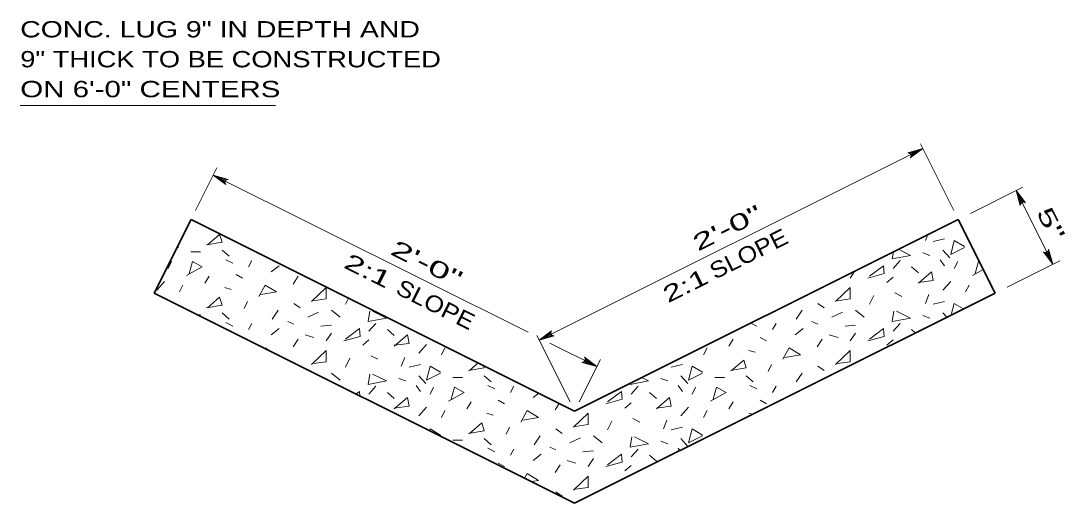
# Model space of a CAD drawing. Extents: x -10 to 104, y -162 to -1.
# Drawn here: x 35.7 to 99, y -82.7 to -53.5 of the extents above; entities that cross this region are included whole.
import ezdxf
from ezdxf.enums import TextEntityAlignment as Align

# ---------------------------------------------------------------- set-up
doc = ezdxf.new("R2010")
doc.units = 0
doc.header["$LTSCALE"] = 0.4
for name, color, linetype, lineweight in [('1', 7, 'Continuous', 35), ('10', 7, 'Continuous', 13), ('12', 7, 'Continuous', 53), ('6', 7, 'Continuous', 13)]:
    doc.layers.add(name, color=color, linetype=linetype, lineweight=lineweight)
doc.layers.add('13', color=7, linetype='Continuous')

msp = doc.modelspace()

# ---------------------------------------------------------------- linework, layer by layer
at = {"layer": '1'}
for p, q in [((46.0245, -65.5251), (69.2796, -77.1526)), ((92.5347, -65.5251), (69.2796, -77.1526)), ((92.5347, -65.5251), (94.7707, -69.9972)), ((94.7707, -69.9972), (69.2796, -82.7428))]:
    msp.add_line(p, q, dxfattribs=at)
at = {"layer": '1', "lineweight": 13}
for p, q in [((83.6592, -75.5428), (83.6702, -75.5475)), ((61.1548, -78.6669), (61.1413, -78.6737))]:
    msp.add_line(p, q, dxfattribs=at)
at = {"layer": '1'}
msp.add_lwpolyline([(46.0245, -65.5251), (43.7884, -69.9972), (69.2796, -82.7428)], dxfattribs=at)
at = {"layer": '10'}
for p, q in [((35.6689, -58.6171), (51.1348, -58.6171)), ((90.385, -61.2257), (67.1299, -72.8532)), ((92.2598, -64.9754), (90.2463, -60.9484)), ((46.2993, -64.9754), (47.5914, -62.3913)), ((47.3701, -62.8338), (66.4527, -72.3751)), ((93.2702, -65.1573), (96.4536, -63.5656)), ((98.275, -68.2451), (96.0389, -63.773)), ((95.5063, -69.6295), (98.6897, -68.0378)), ((69.0047, -76.6029), (66.9912, -72.5759)), ((67.7675, -73.0325), (70.6252, -74.4614)), ((69.5544, -76.6029), (70.8465, -74.0188))]:
    msp.add_line(p, q, dxfattribs=at)
for points in [[(90.385, -61.2257), (89.6295, -61.7988), (89.6714, -61.7222), (89.6766, -61.6497), (89.6583, -61.5891), (89.6207, -61.5379), (89.5596, -61.4986), (89.4732, -61.4862), (90.385, -61.2257), (89.5596, -61.4986), (89.6207, -61.5379), (90.385, -61.2257), (89.6583, -61.5891), (89.6766, -61.6497), (90.385, -61.2257), (89.6714, -61.7222)], [(47.3701, -62.8338), (48.2819, -63.0944), (48.1954, -63.1067), (48.1343, -63.1461), (48.0968, -63.1972), (48.0784, -63.2579), (48.0836, -63.3304), (48.1256, -63.407), (47.3701, -62.8338), (48.0836, -63.3304), (48.0784, -63.2579), (47.3701, -62.8338), (48.0968, -63.1972), (48.1343, -63.1461), (47.3701, -62.8338), (48.1954, -63.1067)], [(96.0389, -63.773), (96.612, -64.5285), (96.5354, -64.4865), (96.463, -64.4813), (96.4023, -64.4997), (96.3511, -64.5372), (96.3118, -64.5983), (96.2994, -64.6848), (96.0389, -63.773), (96.3118, -64.5983), (96.3511, -64.5372), (96.0389, -63.773), (96.4023, -64.4997), (96.463, -64.4813), (96.0389, -63.773), (96.5354, -64.4865)], [(98.275, -68.2451), (97.7018, -67.4896), (97.7785, -67.5316), (97.8509, -67.5367), (97.9116, -67.5184), (97.9627, -67.4808), (98.0021, -67.4198), (98.0144, -67.3333), (98.275, -68.2451), (98.0021, -67.4198), (97.9627, -67.4808), (98.275, -68.2451), (97.9116, -67.5184), (97.8509, -67.5367), (98.275, -68.2451), (97.7785, -67.5316)], [(67.1299, -72.8532), (67.8854, -72.2801), (67.8434, -72.3567), (67.8382, -72.4292), (67.8566, -72.4899), (67.8941, -72.541), (67.9552, -72.5803), (68.0417, -72.5927), (67.1299, -72.8532), (67.9552, -72.5803), (67.8941, -72.541), (67.1299, -72.8532), (67.8566, -72.4899), (67.8382, -72.4292), (67.1299, -72.8532), (67.8434, -72.3567)], [(70.6252, -74.4614), (69.7134, -74.2009), (69.7999, -74.1885), (69.8609, -74.1491), (69.8985, -74.098), (69.9168, -74.0373), (69.9117, -73.9649), (69.8697, -73.8882), (70.6252, -74.4614), (69.9117, -73.9649), (69.9168, -74.0373), (70.6252, -74.4614), (69.8985, -74.098), (69.8609, -74.1491), (70.6252, -74.4614), (69.7999, -74.1885)]]:
    msp.add_lwpolyline(points, dxfattribs=at)
at = {"layer": '6'}
for p, q in [((90.6853, -66.4498), (90.5429, -66.8058)), ((91.6347, -65.9751), (91.6019, -66.0115)), ((91.7078, -66.6999), (91.0194, -66.8587)), ((45.2694, -67.2294), (45.1399, -67.2941)), ((45.2147, -67.1445), (45.2694, -67.1764)), ((46.0108, -67.4941), (46.5932, -67.4941)), ((47.917, -67.3882), (48.3406, -67.7589)), ((90.384, -67.5471), (90.8076, -67.7059)), ((91.6019, -67.3882), (92.0255, -67.8648)), ((44.8458, -68.0766), (44.634, -68.5002)), ((48.1288, -67.9707), (48.5524, -68.1825)), ((49.5056, -68.3943), (49.7174, -68.0237)), ((51.3588, -68.3414), (50.8823, -68.712)), ((88.5837, -68.5002), (89.0073, -68.0237)), ((91.4431, -67.9707), (91.7078, -68.3414)), ((92.5021, -68.0766), (92.2903, -68.5002)), ((46.858, -69.4004), (47.1227, -68.9768)), ((48.7642, -68.8709), (49.1349, -69.0827)), ((52.5238, -68.9768), (52.2061, -69.4533)), ((85.9891, -69.0827), (86.2738, -68.6555)), ((89.6957, -68.3943), (90.1193, -68.765)), ((93.4022, -68.9238), (94.0532, -68.5622)), ((44.4222, -69.2945), (43.9457, -69.824)), ((45.5342, -69.5063), (45.3224, -69.9299)), ((88.213, -69.3474), (88.5837, -69.0297)), ((92.0785, -69.2945), (91.6019, -69.824)), ((93.1904, -69.5063), (92.9786, -69.9299)), ((48.0759, -69.6652), (48.4465, -69.7711)), ((87.154, -70.6712), (87.4187, -70.1417)), ((88.6896, -69.9829), (89.1132, -70.1947)), ((90.7547, -70.0888), (90.5429, -70.6183)), ((49.2408, -70.936), (49.4526, -70.5124)), ((52.259, -70.6183), (52.6297, -70.883)), ((55.3832, -70.6712), (55.5699, -70.2978)), ((84.0299, -70.6183), (84.4005, -70.883)), ((91.7078, -70.5124), (91.0194, -70.6712)), ((46.4072, -71.3066), (46.5932, -71.3066)), ((47.917, -71.2007), (48.3406, -71.5714)), ((51.3059, -71.0419), (50.9352, -71.5714)), ((53.7417, -71.1478), (53.1062, -71.4655)), ((54.5359, -71.0419), (55.0654, -71.4655)), ((83.0767, -71.0419), (82.7061, -71.5714)), ((85.5125, -71.1478), (84.8771, -71.4655)), ((86.3068, -71.0419), (86.8363, -71.4655)), ((90.384, -71.3596), (90.8076, -71.5184)), ((91.6019, -71.2007), (91.8363, -71.4644)), ((48.1288, -71.7832), (48.5524, -71.995)), ((49.5056, -72.2068), (49.7174, -71.8362)), ((51.3588, -72.1539), (50.8823, -72.5245)), ((51.8884, -71.7303), (52.259, -71.8891)), ((53.9005, -71.995), (54.5359, -71.9421)), ((56.8128, -72.3127), (57.2364, -71.8362)), ((79.959, -71.8129), (80.3233, -71.995)), ((81.2764, -72.2068), (81.4882, -71.8362)), ((83.1297, -72.1539), (82.6531, -72.5245)), ((83.6592, -71.7303), (84.0299, -71.8891)), ((85.6713, -71.995), (86.3068, -71.9421)), ((88.5837, -72.3127), (89.0073, -71.8362)), ((52.5238, -72.7893), (52.2061, -73.2658)), ((52.9474, -72.5245), (53.4769, -72.6834)), ((54.2182, -72.8952), (54.5359, -72.4186)), ((57.9248, -72.2068), (58.3484, -72.5775)), ((78.6288, -73.2129), (78.8936, -72.7893)), ((80.5351, -72.6834), (80.9057, -72.8952)), ((84.2946, -72.7893), (83.9769, -73.2658)), ((84.7182, -72.5245), (85.2477, -72.6834)), ((85.9891, -72.8952), (86.3068, -72.4186)), ((89.6957, -72.2068), (89.9342, -72.4155)), ((56.4422, -73.1599), (56.8128, -72.8422)), ((60.3076, -73.107), (59.8311, -73.6365)), ((61.4196, -73.3188), (61.2078, -73.7424)), ((77.305, -73.3188), (77.0932, -73.7424)), ((88.213, -73.1599), (88.5837, -72.8422)), ((55.3832, -74.4837), (55.6479, -73.9542)), ((56.9187, -73.7954), (57.3424, -74.0072)), ((58.9839, -73.9013), (58.7721, -74.4308)), ((79.8467, -73.4777), (80.2173, -73.5836)), ((59.937, -74.3249), (59.2486, -74.4837)), ((63.4413, -74.2335), (62.9022, -74.6955)), ((75.8224, -74.3249), (75.134, -74.4837)), ((81.0116, -74.7485), (81.2234, -74.3249)), ((84.0299, -74.4308), (84.4005, -74.6955)), ((53.7417, -74.9603), (53.7281, -74.9671)), ((54.5359, -74.8544), (55.0654, -75.278)), ((58.6132, -75.1721), (59.0368, -75.3309)), ((59.8311, -75.0132), (60.2547, -75.4898)), ((61.8962, -75.1191), (62.4786, -75.1191)), ((63.8024, -75.0132), (64.226, -75.3839)), ((74.4986, -75.1721), (74.9222, -75.3309)), ((75.7165, -75.0132), (76.1401, -75.4898)), ((77.7816, -75.1191), (78.3641, -75.1191)), ((79.6878, -75.0132), (80.1114, -75.3839)), ((83.0767, -74.8544), (82.7061, -75.3839)), ((56.8128, -76.1252), (57.2364, -75.6487)), ((59.6722, -75.5957), (59.937, -75.9664)), ((60.7312, -75.7016), (60.5194, -76.1252)), ((64.0142, -75.5957), (64.4378, -75.8075)), ((65.391, -76.0193), (65.6028, -75.6487)), ((72.6983, -76.1252), (73.1219, -75.6487)), ((75.5576, -75.5957), (75.8224, -75.9664)), ((76.6167, -75.7016), (76.4048, -76.1252)), ((79.8996, -75.5957), (80.3233, -75.8075)), ((81.2764, -76.0193), (81.4882, -75.6487)), ((57.9248, -76.0193), (58.3484, -76.39)), ((62.7434, -77.0254), (63.0082, -76.6018)), ((64.6497, -76.4959), (65.0203, -76.7077)), ((67.1123, -76.069), (66.7677, -76.337)), ((73.8102, -76.0193), (74.2339, -76.39)), ((78.6288, -77.0254), (78.8936, -76.6018)), ((80.5351, -76.4959), (80.9057, -76.7077)), ((60.3076, -76.9195), (59.8311, -77.449)), ((61.4196, -77.1313), (61.2078, -77.5549)), ((68.3514, -76.6885), (68.0915, -77.0783)), ((72.3276, -76.9724), (72.6983, -76.6547)), ((76.1931, -76.9195), (75.7165, -77.449)), ((77.305, -77.1313), (77.0932, -77.5549)), ((63.9613, -77.2902), (64.3319, -77.3961)), ((71.2686, -78.2962), (71.5333, -77.7667)), ((72.8042, -77.6079), (73.2278, -77.8197)), ((74.8693, -77.7138), (74.6575, -78.2433)), ((79.8467, -77.2902), (80.0619, -77.3516)), ((65.1262, -78.561), (65.338, -78.1374)), ((68.1444, -78.2433), (68.5151, -78.508)), ((75.8224, -78.1374), (75.134, -78.2962)), ((61.8962, -78.9316), (62.4786, -78.9316)), ((63.8024, -78.8257), (64.226, -79.1964)), ((67.1913, -78.6669), (66.8207, -79.1964)), ((69.6271, -78.7728), (68.9917, -79.0905)), ((70.4213, -78.6669), (70.9509, -79.0905)), ((74.4986, -78.9846), (74.9222, -79.1434)), ((75.7165, -78.8257), (76.1401, -79.3023)), ((64.0142, -79.4082), (64.4378, -79.62)), ((65.391, -79.8318), (65.6028, -79.4612)), ((67.7738, -79.3553), (68.1444, -79.5141)), ((69.7859, -79.62), (70.4213, -79.5671)), ((72.6983, -79.9377), (73.1219, -79.4612)), ((75.5576, -79.4082), (75.6606, -79.5523)), ((64.6497, -80.3084), (65.0203, -80.5202)), ((67.2443, -79.7789), (66.7677, -80.1495)), ((68.8328, -80.1495), (69.3623, -80.3084)), ((70.1036, -80.5202), (70.4213, -80.0436)), ((73.8102, -79.8318), (74.2339, -80.2025)), ((68.4092, -80.4143), (68.0915, -80.8908)), ((72.3276, -80.7849), (72.6983, -80.4672)), ((71.5088, -81.6282), (71.5333, -81.5792)), ((68.1444, -82.0558), (68.5151, -82.3205))]:
    msp.add_line(p, q, dxfattribs=at)
for points in [[(46.9639, -67.0705), (47.917, -66.9117), (47.7582, -66.4351), (47.0168, -67.0705)], [(92.9257, -67.2294), (92.0785, -67.653), (92.2903, -66.8058), (92.9257, -67.1764)], [(88.6018, -67.4915), (88.5307, -67.9178), (89.6427, -67.7059), (88.9078, -67.3385)], [(45.746, -68.9238), (46.6991, -68.3943), (46.1167, -68.0766), (45.9048, -68.8179)], [(87.0481, -69.0827), (88.0542, -68.8179), (88.0012, -68.3414), (87.154, -68.9768)], [(93.8245, -68.1048), (93.7729, -68.0766), (93.5611, -68.8179)], [(90.1193, -69.3474), (91.0194, -69.2415), (90.9136, -68.712), (90.1193, -69.4004)], [(50.141, -70.1947), (50.5116, -69.5063), (51.2, -69.9299), (50.2469, -70.0888)], [(46.9639, -70.883), (47.917, -70.7242), (47.7582, -70.2476), (47.0168, -70.883)], [(53.4239, -70.4594), (54.2182, -70.3535), (54.2182, -69.6652), (53.3181, -70.5124)], [(85.1948, -70.4594), (85.9891, -70.3535), (85.9891, -69.6652), (85.0889, -70.5124)], [(92.1134, -71.3259), (92.2903, -70.6183), (92.8618, -70.9517)], [(56.8658, -71.0948), (56.7599, -71.7303), (57.8719, -71.5184), (57.0247, -71.0948)], [(88.6366, -71.0948), (88.5307, -71.7303), (89.6427, -71.5184), (88.7955, -71.0948)], [(55.2773, -72.8952), (56.2833, -72.6304), (56.2304, -72.1539), (55.3832, -72.7893)], [(87.0481, -72.8952), (88.0542, -72.6304), (88.0012, -72.1539), (87.154, -72.7893)], [(58.3484, -73.1599), (59.2486, -73.054), (59.1427, -72.5245), (58.3484, -73.2129)], [(50.4946, -73.3503), (50.5116, -73.3188), (50.8586, -73.5323)], [(81.9118, -74.0072), (82.2825, -73.3188), (82.9708, -73.7424), (82.0177, -73.9013)], [(53.4239, -74.2719), (54.2182, -74.166), (54.2182, -73.4777), (53.3181, -74.3249)], [(78.7347, -74.6955), (79.6878, -74.5367), (79.529, -74.0601), (78.7877, -74.6955)], [(85.1948, -74.2719), (85.9891, -74.166), (85.9891, -73.4777), (85.0889, -74.3249)], [(61.1548, -74.8544), (60.3076, -75.278), (60.5194, -74.4308), (61.1548, -74.8014)], [(62.8493, -74.6955), (63.8024, -74.5367), (63.7534, -74.3895)], [(77.0403, -74.8544), (76.1931, -75.278), (76.4048, -74.4308), (77.0403, -74.8014)], [(56.8658, -74.9073), (56.7599, -75.5428), (57.8719, -75.3309), (57.0247, -74.9073)], [(72.6586, -75.4631), (72.6453, -75.5428), (73.7573, -75.3309), (73.3401, -75.1224)], [(56.26, -76.233), (56.2304, -75.9664), (56.0289, -76.1175)], [(61.6314, -76.5488), (62.5845, -76.0193), (62.0021, -75.7016), (61.7903, -76.4429)], [(71.1627, -76.7077), (72.1687, -76.4429), (72.1158, -75.9664), (71.2686, -76.6018)], [(77.5168, -76.5488), (78.4699, -76.0193), (77.8875, -75.7016), (77.6757, -76.4429)], [(58.3484, -76.9724), (59.2486, -76.8665), (59.1427, -76.337), (58.3484, -77.0254)], [(74.2339, -76.9724), (75.134, -76.8665), (75.0281, -76.337), (74.2339, -77.0254)], [(66.0264, -77.8197), (66.3971, -77.1313), (67.0854, -77.5549), (66.1323, -77.7138)], [(69.3094, -78.0844), (70.1036, -77.9785), (70.1036, -77.2902), (69.2035, -78.1374)], [(60.4929, -78.3495), (60.5194, -78.2433), (61.1548, -78.6139)], [(62.8493, -78.508), (63.8024, -78.3492), (63.6436, -77.8726), (62.9022, -78.508)], [(77.0403, -78.6669), (76.1931, -79.0905), (76.4048, -78.2433), (77.0403, -78.6139)], [(72.7512, -78.7198), (72.6453, -79.3553), (73.7573, -79.1434), (72.9101, -78.7198)], [(71.1627, -80.5202), (72.1687, -80.2554), (72.1158, -79.7789), (71.2686, -80.4143)], [(66.2453, -81.2257), (66.3971, -80.9438), (67.0854, -81.3674), (66.6679, -81.437)], [(69.3094, -81.8969), (70.1036, -81.791), (70.1036, -81.1027), (69.2035, -81.9499)]]:
    msp.add_lwpolyline(points, dxfattribs=at)

# ---------------------------------------------------------------- texts
at = {"layer": '12'}
for s, width, p in [('CONC. LUG 9" IN DEPTH AND', 1.3, (35.6689, -54.4821)), ('9" THICK TO BE CONSTRUCTED', 1.25, (35.6689, -56.2971)), ('ON 6\'-0" CENTERS', 1.35, (35.6689, -58.1121))]:
    msp.add_text(s, height=0.99, dxfattribs=dict(at, width=width)).set_placement(p)
at = {"layer": '12', "width": 1.15}
for rotation, p in [(26.565, (80.0517, -68.0582)), (333.435, (60.6297, -71.1295))]:
    msp.add_text('SLOPE', height=0.99, rotation=rotation, dxfattribs=at).set_placement(p, align=Align.CENTER)
at = {"layer": '13'}
for s, rotation, width, p in [('2\'-0"', 26.565, 1.7, (78.7552, -66.4815)), ('5"', 296.565, 1.7, (97.7148, -66.0068)), ('2\'-0"', 333.435, 1.75, (60.1019, -68.6407)), ('2:1', 333.435, 1.6, (56.5286, -69.079)), ('2:1', 26.565, 1.55, (76.2127, -69.9777))]:
    msp.add_text(s, height=0.99, rotation=rotation, dxfattribs=dict(at, width=width)).set_placement(p, align=Align.CENTER)

doc.saveas('drawing.dxf')
